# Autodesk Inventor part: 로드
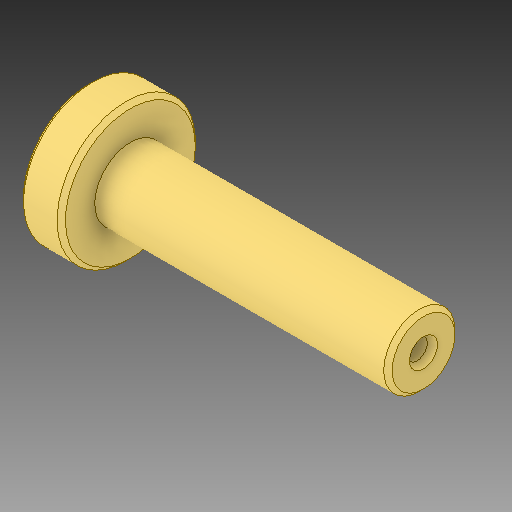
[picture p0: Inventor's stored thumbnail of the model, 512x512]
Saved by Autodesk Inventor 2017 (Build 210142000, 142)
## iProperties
Created: 2024-09
Part Number: 로드
Material: 일반
Document SubType Name: Modeling
Designer: MRC
Density: 1 g/cm^3
Appearance: 기본값
Author: jhkim
Sending System: Autodesk Inventor 2025
Preprocessor: ST-DEVELOPER v20
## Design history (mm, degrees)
feature "솔리드1"
node "솔리드2"
